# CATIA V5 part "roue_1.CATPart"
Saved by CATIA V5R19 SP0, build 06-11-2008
Part number: skl_roue_1
Publications: "axe_pivot_roue1_batit", "lineaire_rect_roue1_sabot1", "Plan.1", "contour_roue1"
Bounding box of the stored display mesh (mm): x 233.168 to 766.832, y 3.332 to 536.668, z -20 to 20
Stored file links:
  C:\Users\Thibaud\Desktop\IFMA\thinkmotion\IAO\modele_catia\squelette\roue_1.CATPart
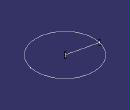
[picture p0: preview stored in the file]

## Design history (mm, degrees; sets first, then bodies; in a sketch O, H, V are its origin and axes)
Body1 (main body)
  Point1: stored without definition
  Point2: stored without definition
  Line1: type PtPt, SecondPoint Point2, FirstPoint Point1
  Plane1: stored without definition
  Point3: stored without definition
  Line2 "axe_pivot_roue1_batit": type Normal, RefSkin Plane1, Start -20, End 20, RefPoint Point3
  Plane2: stored without definition
  Point4: stored without definition
  Line3 "lineaire_rect_roue1_sabot1": type Normal, RefSkin Plane2, Start -20, End 20, RefPoint Point4
  Point5: stored without definition
  Point6: stored without definition
  Plane3: stored without definition
  Circle1 "contour_roue1": type CtrPt, Start 0, End 180, Support Plane3, Center Point5, RefPoint Point6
